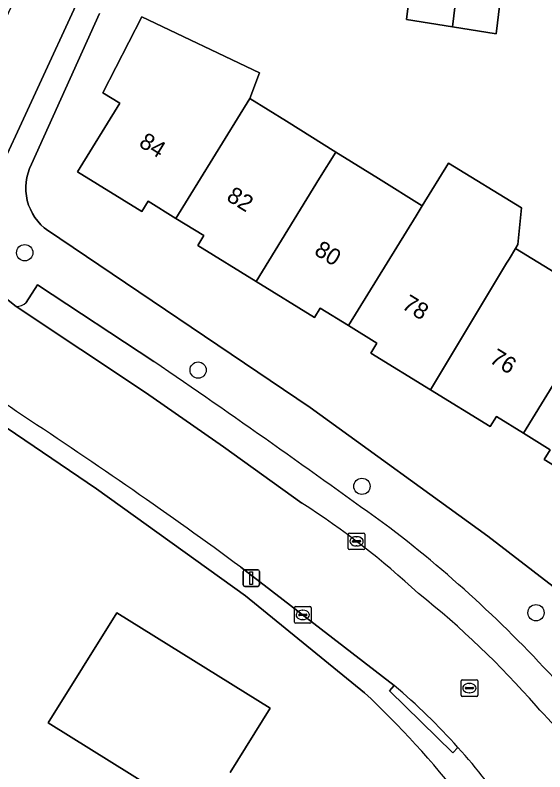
# Model space of a CAD drawing. Extents: x 161692 to 162379, y 380760 to 381678.
# Drawn here: x 161888.02 to 161919.85, y 381012.5 to 381057.99 of the extents above; entities that cross this region are included whole.
import ezdxf

# ---------------------------------------------------------------- set-up
doc = ezdxf.new("R2010")
doc.units = 0
for name, color, linetype in [('IMGEO_Boom', 7, 'Continuous'), ('IMGEO_Erf', 7, 'Continuous'), ('IMGEO_Kolk', 7, 'Continuous'), ('IMGEO_Lichtmast', 7, 'Continuous'), ('IMGEO_Pand', 7, 'Continuous'), ('IMGEO_Pand_nummerreeks', 7, 'Continuous'), ('IMGEO_Parkeervlak_open', 7, 'Continuous'), ('IMGEO_Rijbaan_lokaal_open', 7, 'Continuous'), ('IMGEO_Rioolput', 7, 'Continuous'), ('IMGEO_Voetpad_open', 7, 'Continuous')]:
    doc.layers.add(name, color=color, linetype=linetype)

msp = doc.modelspace()

# ---------------------------------------------------------------- linework, layer by layer
at = {"layer": 'IMGEO_Boom'}
for centre in [(161888.592, 381043.707), (161899.015, 381036.65), (161908.859, 381029.663), (161919.317, 381022.065)]:
    msp.add_circle(centre, 0.489, dxfattribs=at)
at = {"layer": 'IMGEO_Erf'}
for points in [[(161917.362, 381060.521), (161916.914, 381056.87), (161914.299, 381057.291), (161911.543, 381057.735), (161912.118, 381062.433)], [(161909.012, 381017.255), (161901.853, 381023.073), (161892.907, 381029.507), (161882.643, 381036.459), (161870.723, 381044.134), (161860.683, 381050.137), (161858.317, 381051.533), (161845.401, 381058.686)], [(161893.094, 381058.084), (161889.005, 381049.024), (161888.888, 381048.769), (161888.795, 381048.505), (161888.725, 381048.233), (161888.68, 381047.957), (161888.66, 381047.677), (161888.665, 381047.397), (161888.694, 381047.118), (161888.749, 381046.843), (161888.828, 381046.574), (161888.931, 381046.314), (161889.056, 381046.063), (161889.204, 381045.825), (161889.372, 381045.601), (161889.56, 381045.392), (161889.765, 381045.201), (161889.895, 381045.097), (161905.751, 381034.399), (161916.42, 381026.67), (161932.395, 381014.373)], [(161923.395, 381029.081), (161919.818, 381031.283), (161920.176, 381031.865), (161918.558, 381032.86), (161916.94, 381033.856), (161916.572, 381033.257), (161912.981, 381035.467), (161909.391, 381037.677), (161909.758, 381038.273), (161908.055, 381039.321), (161906.349, 381040.371), (161906.01, 381039.821), (161902.5, 381041.982), (161898.992, 381044.141), (161899.36, 381044.739), (161897.681, 381045.772), (161896.006, 381046.803), (161895.628, 381046.189), (161891.757, 381048.571), (161894.299, 381052.701), (161893.286, 381053.325), (161895.63, 381057.892), (161902.711, 381054.516), (161902.114, 381052.975), (161904.32, 381051.618), (161907.287, 381049.76), (161909.843, 381048.16), (161912.486, 381046.533), (161914.061, 381049.096), (161918.438, 381046.402), (161918.231, 381044.2), (161918.09, 381043.966), (161920.768, 381042.317)], [(161901.316, 381008.393), (161889.997, 381015.45), (161894.124, 381022.068), (161903.336, 381016.319), (161900.931, 381012.461)]]:
    msp.add_lwpolyline(points, dxfattribs=at)
msp.add_arc((161870.828, 380976.54), 55.819, 37.8575, 46.8372, dxfattribs=at)
at = {"layer": 'IMGEO_Kolk'}
for p, q in [((161908.033, 381025.93), (161908.033, 381026.782)), ((161908.108, 381026.856), (161908.96, 381026.856)), ((161908.521, 381026.636), (161908.546, 381026.636)), ((161909.034, 381026.782), (161909.034, 381025.93)), ((161908.292, 381026.35), (161908.292, 381026.362)), ((161908.73, 381026.313), (161908.332, 381026.313)), ((161908.335, 381026.399), (161908.733, 381026.399)), ((161908.544, 381026.076), (161908.519, 381026.076)), ((161908.776, 381026.362), (161908.776, 381026.35)), ((161908.96, 381025.856), (161908.108, 381025.856)), ((161904.877, 381022.432), (161905.729, 381022.432)), ((161904.802, 381021.506), (161904.802, 381022.358)), ((161905.104, 381021.975), (161905.502, 381021.975)), ((161905.29, 381022.212), (161905.315, 381022.212)), ((161905.803, 381022.358), (161905.803, 381021.506)), ((161905.061, 381021.926), (161905.061, 381021.938)), ((161905.499, 381021.889), (161905.101, 381021.889)), ((161905.313, 381021.652), (161905.288, 381021.652)), ((161905.545, 381021.938), (161905.545, 381021.926)), ((161905.729, 381021.432), (161904.877, 381021.432))]:
    msp.add_line(p, q, dxfattribs=at)
for points in [[(161908.033, 381025.93), (161908.033, 381026.782)], [(161908.108, 381026.856), (161908.96, 381026.856)], [(161909.034, 381026.782), (161909.034, 381025.93)], [(161908.96, 381025.856), (161908.108, 381025.856)], [(161904.877, 381022.432), (161905.729, 381022.432)], [(161904.802, 381021.506), (161904.802, 381022.358)], [(161905.803, 381022.358), (161905.803, 381021.506)], [(161905.729, 381021.432), (161904.877, 381021.432)]]:
    msp.add_lwpolyline(points, dxfattribs=at)
for centre, radius, start, end in [((161908.11, 381026.78), 0.0765, 91.552, 178.448), ((161908.11, 381026.78), 0.0765, 91.552, 178.448), ((161908.958, 381026.78), 0.0765, 1.552, 88.448), ((161908.958, 381026.78), 0.0765, 1.552, 88.448), ((161908.332, 381026.359), 0.0403, 85.8775, 175.7526), ((161908.329, 381026.349), 0.0366, 178.938, 274.7102), ((161908.733, 381026.356), 0.043, 264.8664, 352.4533), ((161908.737, 381026.361), 0.0386, 1.7309, 96.639), ((161908.11, 381025.932), 0.0765, 181.552, 268.448), ((161908.11, 381025.932), 0.0765, 181.552, 268.448), ((161908.958, 381025.932), 0.0765, 271.552, 358.448), ((161908.958, 381025.932), 0.0765, 271.552, 358.448), ((161904.879, 381022.356), 0.0765, 91.552, 178.448), ((161904.879, 381022.356), 0.0765, 91.552, 178.448), ((161905.727, 381022.356), 0.0765, 1.552, 88.448), ((161905.727, 381022.356), 0.0765, 1.552, 88.448), ((161905.101, 381021.935), 0.0403, 85.8775, 175.7526), ((161905.506, 381021.937), 0.0386, 1.7309, 96.639), ((161905.098, 381021.925), 0.0366, 178.938, 274.7102), ((161905.502, 381021.932), 0.043, 264.8664, 352.4533), ((161904.879, 381021.508), 0.0765, 181.552, 268.448), ((161904.879, 381021.508), 0.0765, 181.552, 268.448), ((161905.727, 381021.508), 0.0765, 271.552, 358.448), ((161905.727, 381021.508), 0.0765, 271.552, 358.448)]:
    msp.add_arc(centre, radius, start, end, dxfattribs=at)
for centre, major_axis, ratio, start_param, end_param in [((161908.52, 381026.356), (-0.387, 0.002), 0.722429, 4.712389, 7.853982), ((161908.545, 381026.356), (-0.39, 0.002), 0.717154, 1.570796, 4.712389), ((161905.289, 381021.932), (-0.387, 0.002), 0.722429, 4.712389, 7.853982), ((161905.314, 381021.932), (-0.39, 0.002), 0.717154, 1.570796, 4.712389)]:
    msp.add_ellipse(centre, major_axis=major_axis, ratio=ratio, start_param=start_param, end_param=end_param, dxfattribs=at)
at = {"layer": 'IMGEO_Lichtmast'}
for p, q in [((161901.711, 381023.746), (161901.711, 381024.546)), ((161901.711, 381024.546), (161901.711, 381023.746)), ((161901.811, 381024.646), (161902.601, 381024.646)), ((161902.601, 381024.646), (161901.811, 381024.646)), ((161902.701, 381024.546), (161902.701, 381023.746)), ((161902.701, 381023.746), (161902.701, 381024.546)), ((161902.601, 381023.646), (161901.811, 381023.646)), ((161901.811, 381023.646), (161902.601, 381023.646))]:
    msp.add_line(p, q, dxfattribs=at)
msp.add_lwpolyline([(161902.131, 381024.521), (161902.281, 381024.521), (161902.281, 381023.771), (161902.131, 381023.771), (161902.131, 381024.521)], dxfattribs=at)
for centre, start, end in [((161901.811, 381024.546), 90, 180), ((161901.811, 381024.546), 90, 180), ((161902.601, 381024.546), 0, 90), ((161902.601, 381024.546), 360, 90), ((161901.811, 381023.746), 180, 270), ((161901.811, 381023.746), 180, 270), ((161902.601, 381023.746), 270, 0), ((161902.601, 381023.746), 270, 0)]:
    msp.add_arc(centre, 0.1, start, end, dxfattribs=at)
at = {"layer": 'IMGEO_Pand'}
for points in [[(161914.809, 381061.452), (161912.118, 381062.433), (161911.543, 381057.735), (161914.299, 381057.291)], [(161917.362, 381060.521), (161914.809, 381061.452), (161914.299, 381057.291), (161916.914, 381056.87)], [(161902.711, 381054.516), (161895.63, 381057.892), (161893.286, 381053.325), (161894.299, 381052.701), (161891.757, 381048.571), (161895.628, 381046.189), (161896.006, 381046.803), (161897.681, 381045.772), (161902.114, 381052.975)], [(161897.681, 381045.772), (161899.36, 381044.739), (161898.992, 381044.141), (161902.5, 381041.982), (161906.313, 381048.178), (161907.287, 381049.76), (161904.32, 381051.618), (161902.114, 381052.975)], [(161912.486, 381046.533), (161909.843, 381048.16), (161907.287, 381049.76), (161906.313, 381048.178), (161902.5, 381041.982), (161906.01, 381039.821), (161906.349, 381040.371), (161908.055, 381039.321), (161912.107, 381045.917)], [(161918.09, 381043.966), (161918.231, 381044.2), (161918.438, 381046.402), (161914.061, 381049.096), (161912.486, 381046.533), (161912.107, 381045.917), (161908.055, 381039.321), (161909.758, 381038.273), (161909.391, 381037.677), (161912.981, 381035.467), (161917.552, 381043.07), (161917.703, 381043.322)], [(161922.995, 381040.073), (161920.378, 381041.684), (161920.768, 381042.317), (161918.09, 381043.966), (161917.703, 381043.322), (161917.552, 381043.07), (161912.981, 381035.467), (161916.572, 381033.257), (161916.94, 381033.856), (161918.558, 381032.86)], [(161918.558, 381032.86), (161920.176, 381031.865), (161919.818, 381031.283), (161923.395, 381029.081), (161927.231, 381035.309), (161928.914, 381038.042), (161926.13, 381039.756), (161925.41, 381038.587), (161922.995, 381040.073)]]:
    msp.add_lwpolyline(points, close=True, dxfattribs=at)
msp.add_lwpolyline([(161900.931, 381012.461), (161903.336, 381016.319), (161894.124, 381022.068), (161889.997, 381015.45), (161901.316, 381008.393)], dxfattribs=at)
at = {"layer": 'IMGEO_Parkeervlak_open'}
for points in [[(161896.352, 381037.168), (161889.37, 381041.768), (161888.682, 381040.716)], [(161888.082, 381040.475), (161895.843, 381035.294), (161900.546, 381032.038), (161905.254, 381028.641)]]:
    msp.add_lwpolyline(points, dxfattribs=at)
for centre, radius, start, end in [((161888.095, 381041.31), 0.835, 269.1184, 314.649), ((161547.991, 380528.239), 616.737, 53.996333, 55.608468), ((161879.524, 380988.225), 47.911, 46.9164, 57.5187), ((161864.92, 380967.493), 75.109, 41.72193, 52.60698), ((161878.987, 380981.313), 53.502, 41.0703, 51.5567), ((161827.755, 380930.818), 125.378, 38.12777, 43.08627)]:
    msp.add_arc(centre, radius, start, end, dxfattribs=at)
at = {"layer": 'IMGEO_Rijbaan_lokaal_open'}
msp.add_lwpolyline([(161901.665, 381108.723), (161902.009, 381111.747), (161901.747, 381112.421), (161899.888, 381112.731), (161893.576, 381129.276), (161890.302, 381128.132), (161892.607, 381122.097), (161896.009, 381113.169), (161895.912, 381112.139), (161894.473, 381099.213), (161894.31, 381097.589), (161892.263, 381079.432), (161892.097, 381078.052), (161891.241, 381070.22), (161890.614, 381064.695), (161887.953, 381058.917), (161885.89, 381054.437), (161883.582, 381049.424), (161886.556, 381047.541), (161894.574, 381064.871), (161896.026, 381069.305), (161896.944, 381069.188), (161897.356, 381072.208)], close=True, dxfattribs=at)
for points in [[(161905.254, 381028.641), (161900.546, 381032.038), (161895.843, 381035.294), (161888.082, 381040.475), (161886.889, 381041.386), (161886.684, 381041.505), (161882.309, 381044.351), (161877.385, 381047.398), (161874.352, 381049.226), (161863.015, 381055.945), (161859.824, 381057.819), (161857.272, 381053.223), (161858.559, 381052.511), (161858.808, 381052.367), (161861.155, 381050.983), (161861.681, 381050.67)], [(161901.588, 381024.798), (161910.802, 381017.693)]]:
    msp.add_lwpolyline(points, dxfattribs=at)
for centre, radius, start, end in [((161740.289, 380820.096), 260.148, 55.27804, 58.37491), ((161721.349, 380779.505), 304.392, 53.69201, 56.69997), ((161879.524, 380988.225), 47.911, 46.9164, 57.5187), ((161878.987, 380981.313), 53.502, 41.0703, 51.5567), ((161885.399, 380987.774), 39.248, 41.8669, 49.6661), ((161827.755, 380930.818), 125.378, 38.12777, 43.08627), ((161885.32, 380987.728), 39.338, 26.8121, 41.8408)]:
    msp.add_arc(centre, radius, start, end, dxfattribs=at)
at = {"layer": 'IMGEO_Rioolput'}
for p, q in [((161914.815, 381017.11), (161914.815, 381017.962)), ((161914.89, 381018.036), (161915.742, 381018.036)), ((161915.816, 381017.962), (161915.816, 381017.11)), ((161915.074, 381017.53), (161915.074, 381017.542)), ((161915.512, 381017.493), (161915.114, 381017.493)), ((161915.117, 381017.579), (161915.515, 381017.579)), ((161915.303, 381017.816), (161915.328, 381017.816)), ((161915.558, 381017.542), (161915.558, 381017.53)), ((161915.742, 381017.036), (161914.89, 381017.036)), ((161915.326, 381017.256), (161915.301, 381017.256))]:
    msp.add_line(p, q, dxfattribs=at)
for points in [[(161914.815, 381017.11), (161914.815, 381017.962)], [(161914.89, 381018.036), (161915.742, 381018.036)], [(161915.816, 381017.962), (161915.816, 381017.11)], [(161915.742, 381017.036), (161914.89, 381017.036)]]:
    msp.add_lwpolyline(points, dxfattribs=at)
for centre, radius, start, end in [((161914.892, 381017.96), 0.0765, 91.552, 178.448), ((161914.892, 381017.96), 0.0765, 91.552, 178.448), ((161915.74, 381017.96), 0.0765, 1.552, 88.448), ((161915.74, 381017.96), 0.0765, 1.552, 88.448), ((161915.114, 381017.539), 0.0403, 85.8775, 175.7526), ((161915.111, 381017.529), 0.0366, 178.938, 274.7102), ((161915.515, 381017.536), 0.043, 264.8664, 352.4533), ((161915.519, 381017.541), 0.0386, 1.7309, 96.639), ((161914.892, 381017.112), 0.0765, 181.552, 268.448), ((161914.892, 381017.112), 0.0765, 181.552, 268.448), ((161915.74, 381017.112), 0.0765, 271.552, 358.448), ((161915.74, 381017.112), 0.0765, 271.552, 358.448)]:
    msp.add_arc(centre, radius, start, end, dxfattribs=at)
for centre, major_axis, ratio, start_param, end_param in [((161915.302, 381017.536), (-0.387, 0.002), 0.722429, 4.712389, 7.853982), ((161915.327, 381017.536), (-0.39, 0.002), 0.717154, 1.570796, 4.712389)]:
    msp.add_ellipse(centre, major_axis=major_axis, ratio=ratio, start_param=start_param, end_param=end_param, dxfattribs=at)
at = {"layer": 'IMGEO_Voetpad_open'}
for points in [[(161894.574, 381064.871), (161886.556, 381047.541), (161883.582, 381049.424), (161858.502, 381064.372)], [(161932.395, 381014.373), (161916.42, 381026.67), (161905.751, 381034.399), (161889.895, 381045.097), (161889.765, 381045.201), (161889.56, 381045.392), (161889.372, 381045.601), (161889.204, 381045.825), (161889.056, 381046.063), (161888.931, 381046.314), (161888.828, 381046.574), (161888.749, 381046.843), (161888.694, 381047.118), (161888.665, 381047.397), (161888.66, 381047.677), (161888.68, 381047.957), (161888.725, 381048.233), (161888.795, 381048.505), (161888.888, 381048.769), (161889.005, 381049.024), (161893.094, 381058.084)], [(161861.681, 381050.67), (161860.683, 381050.137), (161870.723, 381044.134), (161882.643, 381036.459), (161892.907, 381029.507), (161901.853, 381023.073), (161909.012, 381017.255)], [(161874.352, 381049.226), (161877.385, 381047.398), (161877.934, 381048.28), (161882.605, 381045.377), (161887.226, 381042.378), (161886.684, 381041.505), (161886.889, 381041.386), (161888.082, 381040.475)], [(161888.682, 381040.716), (161889.37, 381041.768), (161896.352, 381037.168)], [(161914.627, 381013.969), (161914.314, 381013.641), (161910.523, 381017.366), (161910.802, 381017.693), (161901.588, 381024.798)], [(161910.802, 381017.693), (161910.523, 381017.366), (161914.314, 381013.641), (161914.627, 381013.969)]]:
    msp.add_lwpolyline(points, dxfattribs=at)
for centre, radius, start, end in [((161740.289, 380820.096), 260.148, 55.27804, 58.37491), ((161888.095, 381041.31), 0.835, 269.1184, 314.649), ((161547.991, 380528.239), 616.737, 53.996333, 55.608468), ((161721.349, 380779.505), 304.392, 53.69201, 56.69997), ((161864.92, 380967.493), 75.109, 41.72193, 52.60698), ((161885.399, 380987.774), 39.248, 41.8669, 49.6661), ((161870.828, 380976.54), 55.819, 37.8575, 46.8372), ((161885.32, 380987.728), 39.338, 26.8121, 41.8408)]:
    msp.add_arc(centre, radius, start, end, dxfattribs=at)

# ---------------------------------------------------------------- texts
at = {"layer": 'IMGEO_Pand_nummerreeks'}
for s, rotation, p in [('84', 328.3387, (161895.388, 381050.139)), ('82', 328.3387, (161900.654, 381046.892)), ('80', 328.3384, (161905.926, 381043.641)), ('78', 328.3384, (161911.194, 381040.393)), ('76', 328.3384, (161916.459, 381037.146))]:
    msp.add_text(s, height=1, rotation=rotation, dxfattribs=at).set_placement(p)

doc.saveas('drawing.dxf')
